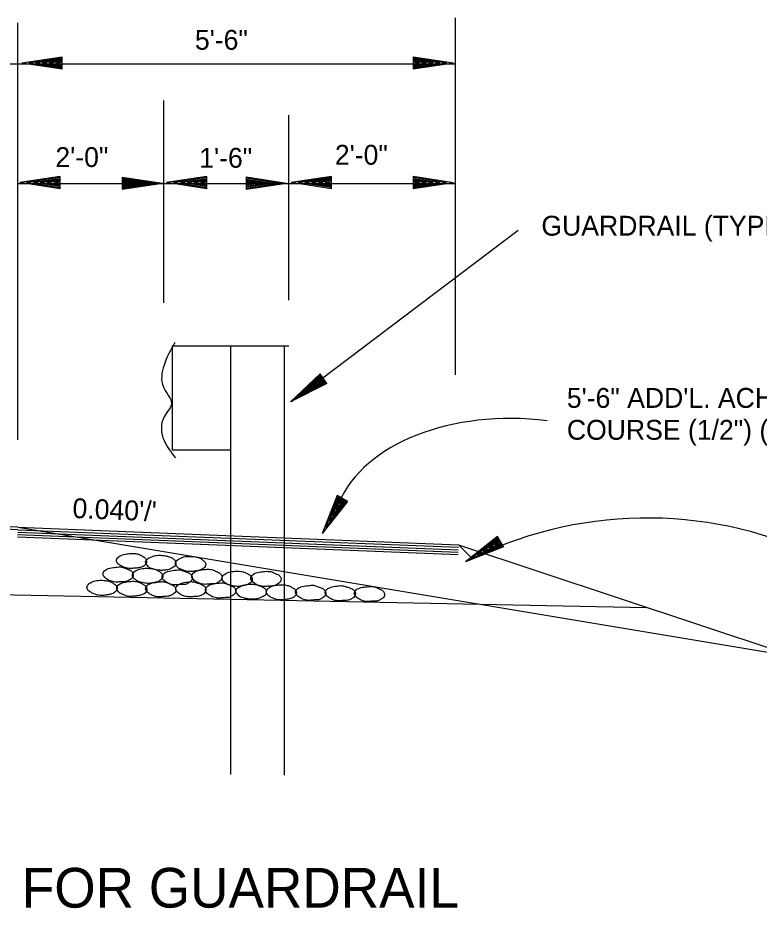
# Model space of a CAD drawing. Extents: x 1373918 to 1374069, y 381000 to 381245.
# Drawn here: x 1373981.14 to 1374003.52, y 381205.43 to 381232.33 of the extents above; entities that cross this region are included whole.
import ezdxf

# ---------------------------------------------------------------- set-up
doc = ezdxf.new("R2010")
doc.units = 0
doc.layers.add('Default', color=7, linetype='Continuous')

msp = doc.modelspace()

# ---------------------------------------------------------------- linework, layer by layer
at = {"layer": 'Default'}
for p, q in [((1373994.349, 381221.542), (1373994.349, 381232.331)), ((1373981.145, 381219.578), (1373981.145, 381232.175)), ((1373961.705, 381230.94), (1373994.349, 381230.94)), ((1373982.481, 381231.144), (1373981.264, 381230.962)), ((1373982.481, 381230.777), (1373981.264, 381230.962)), ((1373982.481, 381231.113), (1373981.468, 381230.962)), ((1373982.481, 381230.809), (1373981.468, 381230.962)), ((1373982.481, 381231.081), (1373981.677, 381230.962)), ((1373982.481, 381230.841), (1373981.677, 381230.962)), ((1373982.481, 381231.052), (1373981.881, 381230.962)), ((1373982.481, 381230.87), (1373981.881, 381230.962)), ((1373982.481, 381231.02), (1373982.085, 381230.962)), ((1373982.481, 381230.901), (1373982.085, 381230.962)), ((1373982.481, 381230.989), (1373982.289, 381230.962)), ((1373982.481, 381230.933), (1373982.289, 381230.962)), ((1373982.481, 381230.777), (1373982.481, 381231.144)), ((1373993.071, 381231.157), (1373994.288, 381230.972)), ((1373993.071, 381231.157), (1373993.071, 381230.79)), ((1373993.071, 381231.125), (1373994.084, 381230.972)), ((1373993.071, 381231.093), (1373993.875, 381230.972)), ((1373993.071, 381231.064), (1373993.671, 381230.972)), ((1373993.071, 381231.033), (1373993.467, 381230.972)), ((1373993.071, 381231.001), (1373993.263, 381230.972)), ((1373993.071, 381230.79), (1373994.288, 381230.972)), ((1373993.071, 381230.914), (1373993.467, 381230.972)), ((1373993.071, 381230.853), (1373993.875, 381230.972)), ((1373993.071, 381230.821), (1373994.084, 381230.972)), ((1373993.071, 381230.882), (1373993.671, 381230.972)), ((1373993.071, 381230.945), (1373993.263, 381230.972)), ((1373985.545, 381223.724), (1373985.545, 381229.835)), ((1373989.319, 381223.803), (1373989.319, 381229.39)), ((1373982.415, 381227.533), (1373981.198, 381227.351)), ((1373982.415, 381227.502), (1373981.402, 381227.351)), ((1373982.415, 381227.47), (1373981.611, 381227.351)), ((1373982.415, 381227.441), (1373981.815, 381227.351)), ((1373982.415, 381227.409), (1373982.019, 381227.351)), ((1373982.415, 381227.166), (1373982.415, 381227.533)), ((1373984.294, 381227.521), (1373985.511, 381227.337)), ((1373984.294, 381227.521), (1373984.294, 381227.154)), ((1373984.294, 381227.49), (1373985.307, 381227.337)), ((1373984.294, 381227.458), (1373985.098, 381227.337)), ((1373984.294, 381227.429), (1373984.894, 381227.337)), ((1373984.294, 381227.397), (1373984.69, 381227.337)), ((1373986.85, 381227.533), (1373985.633, 381227.351)), ((1373986.85, 381227.502), (1373985.837, 381227.351)), ((1373986.85, 381227.47), (1373986.046, 381227.351)), ((1373986.85, 381227.441), (1373986.25, 381227.351)), ((1373986.85, 381227.409), (1373986.454, 381227.351)), ((1373986.85, 381227.166), (1373986.85, 381227.533)), ((1373988.034, 381227.524), (1373989.251, 381227.339)), ((1373988.034, 381227.524), (1373988.034, 381227.157)), ((1373988.034, 381227.492), (1373989.047, 381227.339)), ((1373988.034, 381227.46), (1373988.838, 381227.339)), ((1373988.034, 381227.431), (1373988.634, 381227.339)), ((1373988.034, 381227.4), (1373988.43, 381227.339)), ((1373990.612, 381227.536), (1373989.394, 381227.354)), ((1373990.612, 381227.504), (1373989.599, 381227.354)), ((1373990.612, 381227.473), (1373989.808, 381227.354)), ((1373990.612, 381227.443), (1373990.012, 381227.354)), ((1373990.612, 381227.412), (1373990.216, 381227.354)), ((1373990.612, 381227.169), (1373990.612, 381227.536)), ((1373993.071, 381227.543), (1373994.288, 381227.358)), ((1373993.071, 381227.543), (1373993.071, 381227.176)), ((1373993.071, 381227.512), (1373994.084, 381227.358)), ((1373993.071, 381227.48), (1373993.875, 381227.358)), ((1373993.071, 381227.451), (1373993.671, 381227.358)), ((1373993.071, 381227.419), (1373993.467, 381227.358)), ((1373981.145, 381227.329), (1373994.349, 381227.329)), ((1373982.415, 381227.166), (1373981.198, 381227.351)), ((1373982.415, 381227.198), (1373981.402, 381227.351)), ((1373982.415, 381227.23), (1373981.611, 381227.351)), ((1373982.415, 381227.259), (1373981.815, 381227.351)), ((1373982.415, 381227.29), (1373982.019, 381227.351)), ((1373982.415, 381227.378), (1373982.223, 381227.351)), ((1373982.415, 381227.322), (1373982.223, 381227.351)), ((1373984.294, 381227.366), (1373984.486, 381227.337)), ((1373984.294, 381227.154), (1373985.511, 381227.337)), ((1373984.294, 381227.278), (1373984.69, 381227.337)), ((1373984.294, 381227.217), (1373985.098, 381227.337)), ((1373984.294, 381227.186), (1373985.307, 381227.337)), ((1373984.294, 381227.247), (1373984.894, 381227.337)), ((1373984.294, 381227.31), (1373984.486, 381227.337)), ((1373986.85, 381227.166), (1373985.633, 381227.351)), ((1373986.85, 381227.198), (1373985.837, 381227.351)), ((1373986.85, 381227.23), (1373986.046, 381227.351)), ((1373986.85, 381227.259), (1373986.25, 381227.351)), ((1373986.85, 381227.29), (1373986.454, 381227.351)), ((1373986.85, 381227.378), (1373986.658, 381227.351)), ((1373986.85, 381227.322), (1373986.658, 381227.351)), ((1373988.034, 381227.368), (1373988.226, 381227.339)), ((1373988.034, 381227.157), (1373989.251, 381227.339)), ((1373988.034, 381227.281), (1373988.43, 381227.339)), ((1373988.034, 381227.22), (1373988.838, 381227.339)), ((1373988.034, 381227.188), (1373989.047, 381227.339)), ((1373988.034, 381227.249), (1373988.634, 381227.339)), ((1373988.034, 381227.312), (1373988.226, 381227.339)), ((1373990.612, 381227.169), (1373989.394, 381227.354)), ((1373990.612, 381227.2), (1373989.599, 381227.354)), ((1373990.612, 381227.232), (1373989.808, 381227.354)), ((1373990.612, 381227.261), (1373990.012, 381227.354)), ((1373990.612, 381227.293), (1373990.216, 381227.354)), ((1373990.612, 381227.38), (1373990.42, 381227.354)), ((1373990.612, 381227.324), (1373990.42, 381227.354)), ((1373993.071, 381227.388), (1373993.263, 381227.358)), ((1373993.071, 381227.176), (1373994.288, 381227.358)), ((1373993.071, 381227.3), (1373993.467, 381227.358)), ((1373993.071, 381227.239), (1373993.875, 381227.358)), ((1373993.071, 381227.208), (1373994.084, 381227.358)), ((1373993.071, 381227.269), (1373993.671, 381227.358)), ((1373993.071, 381227.332), (1373993.263, 381227.358)), ((1373989.399, 381220.744), (1373996.245, 381225.917)), ((1373985.798, 381222.423), (1373985.798, 381219.279)), ((1373985.798, 381222.423), (1373989.319, 381222.423)), ((1373987.56, 381222.423), (1373987.56, 381209.466)), ((1373989.178, 381222.409), (1373989.178, 381209.454)), ((1373990.263, 381221.575), (1373989.368, 381220.73)), ((1373990.282, 381221.552), (1373989.534, 381220.844)), ((1373990.302, 381221.522), (1373989.711, 381220.97)), ((1373990.314, 381221.497), (1373989.876, 381221.084)), ((1373990.332, 381221.476), (1373990.041, 381221.201)), ((1373990.469, 381221.279), (1373990.263, 381221.575)), ((1373990.469, 381221.279), (1373989.368, 381220.73)), ((1373990.455, 381221.301), (1373989.534, 381220.844)), ((1373990.433, 381221.328), (1373989.711, 381220.97)), ((1373990.416, 381221.354), (1373989.876, 381221.084)), ((1373990.396, 381221.381), (1373990.041, 381221.201)), ((1373990.349, 381221.449), (1373990.209, 381221.318)), ((1373990.384, 381221.408), (1373990.209, 381221.318)), ((1373985.798, 381219.279), (1373987.56, 381219.279)), ((1373990.78, 381217.903), (1373990.328, 381216.756)), ((1373991.095, 381217.719), (1373990.328, 381216.756)), ((1373990.804, 381217.884), (1373990.43, 381216.934)), ((1373991.071, 381217.736), (1373990.43, 381216.934)), ((1373990.833, 381217.869), (1373990.534, 381217.116)), ((1373991.04, 381217.748), (1373990.534, 381217.116)), ((1373990.857, 381217.855), (1373990.634, 381217.289)), ((1373991.015, 381217.765), (1373990.634, 381217.289)), ((1373990.886, 381217.84), (1373990.738, 381217.468)), ((1373990.989, 381217.779), (1373990.738, 381217.468)), ((1373991.095, 381217.719), (1373990.78, 381217.903)), ((1373990.916, 381217.823), (1373990.843, 381217.643)), ((1373990.962, 381217.796), (1373990.843, 381217.643)), ((1373981.145, 381216.939), (1373966.565, 381217.522)), ((1373981.145, 381216.866), (1373966.565, 381217.449)), ((1373981.145, 381216.939), (1373994.444, 381216.406)), ((1373981.145, 381216.939), (1374004.609, 381213.026)), ((1373981.132, 381216.647), (1373994.432, 381216.115)), ((1373981.135, 381216.72), (1373994.434, 381216.188)), ((1373981.138, 381216.793), (1373994.437, 381216.261)), ((1373981.141, 381216.866), (1373994.44, 381216.334)), ((1373995.615, 381216.666), (1373994.653, 381215.899)), ((1373995.632, 381216.637), (1373994.83, 381215.998)), ((1373995.8, 381216.348), (1373995.615, 381216.666)), ((1373994.444, 381216.406), (1374010.555, 381211.051)), ((1373994.444, 381216.406), (1373994.862, 381215.991)), ((1373995.783, 381216.375), (1373994.83, 381215.998)), ((1373995.647, 381216.611), (1373995.01, 381216.105)), ((1373995.766, 381216.402), (1373995.01, 381216.105)), ((1373995.661, 381216.586), (1373995.185, 381216.207)), ((1373995.751, 381216.426), (1373995.185, 381216.207)), ((1373995.676, 381216.557), (1373995.363, 381216.309)), ((1373995.737, 381216.453), (1373995.363, 381216.309)), ((1373995.693, 381216.53), (1373995.542, 381216.411)), ((1373995.722, 381216.482), (1373995.542, 381216.411)), ((1373995.8, 381216.348), (1373994.653, 381215.899)), ((1373961.266, 381215.293), (1374000.118, 381214.521))]:
    msp.add_line(p, q, dxfattribs=at)
msp.add_arc((1374000.135, 381205.199), 12.021, 64.8876, 117.1378, dxfattribs=at)
msp.add_ellipse((1373996.638, 381216.221), major_axis=(-6.005, 0.733), ratio=0.655798, start_param=4.712389, end_param=6.093533, dxfattribs=at)
for points in [[(1373985.883, 381222.525), (1373985.553, 381221.842), (1373985.536, 381221.177), (1373985.774, 381220.664), (1373985.553, 381220.275), (1373985.553, 381219.558), (1373985.903, 381219.041)], [(1373984.588, 381216.147), (1373984.428, 381216.137), (1373984.233, 381216.079), (1373984.131, 381215.987), (1373984.116, 381215.933), (1373984.165, 381215.836), (1373984.223, 381215.792), (1373984.335, 381215.739), (1373984.491, 381215.695), (1373984.573, 381215.695), (1373984.69, 381215.705), (1373984.821, 381215.72), (1373984.923, 381215.758), (1373985.011, 381215.841), (1373985.025, 381215.904), (1373984.996, 381215.992), (1373984.933, 381216.05), (1373984.865, 381216.089), (1373984.758, 381216.133), (1373984.69, 381216.147), (1373984.588, 381216.147)], [(1373985.459, 381216.095), (1373985.298, 381216.086), (1373985.109, 381216.018), (1373985.012, 381215.94), (1373984.997, 381215.886), (1373985.05, 381215.784), (1373985.094, 381215.731), (1373985.211, 381215.682), (1373985.357, 381215.648), (1373985.439, 381215.639), (1373985.561, 381215.643), (1373985.697, 381215.668), (1373985.794, 381215.711), (1373985.896, 381215.789), (1373985.911, 381215.852), (1373985.881, 381215.94), (1373985.809, 381216.003), (1373985.736, 381216.037), (1373985.629, 381216.071), (1373985.561, 381216.086), (1373985.459, 381216.095)], [(1373986.365, 381216.059), (1373986.205, 381216.054), (1373986.01, 381215.986), (1373985.913, 381215.899), (1373985.898, 381215.84), (1373985.952, 381215.743), (1373986.005, 381215.699), (1373986.112, 381215.651), (1373986.268, 381215.607), (1373986.35, 381215.602), (1373986.467, 381215.612), (1373986.598, 381215.636), (1373986.7, 381215.675), (1373986.798, 381215.753), (1373986.812, 381215.811), (1373986.783, 381215.899), (1373986.71, 381215.957), (1373986.642, 381216.005), (1373986.535, 381216.039), (1373986.467, 381216.054), (1373986.365, 381216.059)], [(1373984.185, 381215.741), (1373984.015, 381215.722), (1373983.826, 381215.673), (1373983.728, 381215.581), (1373983.714, 381215.528), (1373983.762, 381215.426), (1373983.821, 381215.382), (1373983.928, 381215.323), (1373984.083, 381215.285), (1373984.161, 381215.285), (1373984.283, 381215.294), (1373984.419, 381215.304), (1373984.521, 381215.353), (1373984.608, 381215.435), (1373984.623, 381215.498), (1373984.594, 381215.586), (1373984.521, 381215.644), (1373984.453, 381215.673), (1373984.346, 381215.717), (1373984.283, 381215.737), (1373984.185, 381215.741)], [(1373985.067, 381215.7), (1373984.907, 381215.695), (1373984.713, 381215.632), (1373984.615, 381215.54), (1373984.601, 381215.486), (1373984.654, 381215.384), (1373984.708, 381215.34), (1373984.815, 381215.292), (1373984.97, 381215.253), (1373985.053, 381215.243), (1373985.169, 381215.253), (1373985.301, 381215.277), (1373985.403, 381215.316), (1373985.5, 381215.394), (1373985.515, 381215.457), (1373985.485, 381215.545), (1373985.412, 381215.603), (1373985.344, 381215.647), (1373985.238, 381215.681), (1373985.169, 381215.695), (1373985.067, 381215.7)], [(1373985.966, 381215.651), (1373985.805, 381215.636), (1373985.611, 381215.583), (1373985.509, 381215.49), (1373985.494, 381215.437), (1373985.548, 381215.34), (1373985.601, 381215.296), (1373985.713, 381215.233), (1373985.864, 381215.199), (1373985.946, 381215.199), (1373986.063, 381215.208), (1373986.204, 381215.213), (1373986.301, 381215.262), (1373986.393, 381215.345), (1373986.408, 381215.408), (1373986.379, 381215.495), (1373986.311, 381215.553), (1373986.238, 381215.588), (1373986.136, 381215.622), (1373986.068, 381215.651), (1373985.966, 381215.651)], [(1373986.85, 381215.673), (1373986.69, 381215.654), (1373986.5, 381215.605), (1373986.403, 381215.513), (1373986.389, 381215.46), (1373986.442, 381215.357), (1373986.495, 381215.314), (1373986.602, 381215.255), (1373986.758, 381215.217), (1373986.836, 381215.217), (1373986.957, 381215.226), (1373987.088, 381215.236), (1373987.195, 381215.285), (1373987.288, 381215.367), (1373987.302, 381215.43), (1373987.273, 381215.518), (1373987.2, 381215.576), (1373987.127, 381215.605), (1373987.025, 381215.654), (1373986.952, 381215.669), (1373986.85, 381215.673)], [(1373987.769, 381215.61), (1373987.608, 381215.605), (1373987.414, 381215.542), (1373987.317, 381215.45), (1373987.302, 381215.396), (1373987.356, 381215.294), (1373987.409, 381215.251), (1373987.516, 381215.202), (1373987.672, 381215.163), (1373987.754, 381215.153), (1373987.871, 381215.163), (1373988.002, 381215.187), (1373988.104, 381215.226), (1373988.201, 381215.304), (1373988.216, 381215.367), (1373988.187, 381215.455), (1373988.114, 381215.513), (1373988.046, 381215.557), (1373987.939, 381215.591), (1373987.871, 381215.605), (1373987.769, 381215.61)], [(1373988.635, 381215.61), (1373988.474, 381215.591), (1373988.285, 381215.542), (1373988.188, 381215.45), (1373988.173, 381215.396), (1373988.226, 381215.294), (1373988.28, 381215.251), (1373988.387, 381215.192), (1373988.542, 381215.153), (1373988.62, 381215.153), (1373988.742, 381215.163), (1373988.873, 381215.173), (1373988.98, 381215.221), (1373989.072, 381215.304), (1373989.087, 381215.367), (1373989.057, 381215.455), (1373988.985, 381215.513), (1373988.912, 381215.542), (1373988.81, 381215.591), (1373988.737, 381215.605), (1373988.635, 381215.61)], [(1373983.69, 381215.337), (1373983.529, 381215.332), (1373983.335, 381215.264), (1373983.242, 381215.177), (1373983.228, 381215.119), (1373983.276, 381215.021), (1373983.335, 381214.978), (1373983.437, 381214.929), (1373983.597, 381214.885), (1373983.675, 381214.88), (1373983.797, 381214.89), (1373983.928, 381214.914), (1373984.03, 381214.953), (1373984.122, 381215.031), (1373984.137, 381215.089), (1373984.108, 381215.177), (1373984.035, 381215.235), (1373983.967, 381215.284), (1373983.86, 381215.318), (1373983.792, 381215.332), (1373983.69, 381215.337)], [(1373984.589, 381215.309), (1373984.428, 381215.294), (1373984.234, 381215.236), (1373984.142, 381215.148), (1373984.127, 381215.09), (1373984.176, 381214.993), (1373984.224, 381214.949), (1373984.336, 381214.901), (1373984.487, 381214.852), (1373984.569, 381214.852), (1373984.691, 381214.862), (1373984.827, 381214.881), (1373984.924, 381214.915), (1373985.021, 381215.003), (1373985.036, 381215.061), (1373985.007, 381215.148), (1373984.934, 381215.207), (1373984.861, 381215.251), (1373984.759, 381215.289), (1373984.691, 381215.304), (1373984.589, 381215.309)], [(1373985.463, 381215.296), (1373985.302, 381215.276), (1373985.108, 381215.223), (1373985.011, 381215.136), (1373984.996, 381215.077), (1373985.05, 381214.98), (1373985.103, 381214.936), (1373985.21, 381214.878), (1373985.361, 381214.839), (1373985.443, 381214.839), (1373985.565, 381214.849), (1373985.696, 381214.859), (1373985.798, 381214.902), (1373985.895, 381214.99), (1373985.91, 381215.048), (1373985.881, 381215.136), (1373985.808, 381215.194), (1373985.735, 381215.228), (1373985.628, 381215.267), (1373985.565, 381215.291), (1373985.463, 381215.296)], [(1373986.377, 381215.297), (1373986.212, 381215.277), (1373986.018, 381215.224), (1373985.92, 381215.136), (1373985.906, 381215.078), (1373985.959, 381214.981), (1373986.013, 381214.937), (1373986.124, 381214.874), (1373986.275, 381214.84), (1373986.353, 381214.84), (1373986.474, 381214.845), (1373986.61, 381214.859), (1373986.713, 381214.903), (1373986.805, 381214.991), (1373986.819, 381215.049), (1373986.79, 381215.136), (1373986.717, 381215.195), (1373986.644, 381215.229), (1373986.542, 381215.263), (1373986.479, 381215.282), (1373986.377, 381215.297)], [(1373987.273, 381215.26), (1373987.103, 381215.241), (1373986.918, 381215.192), (1373986.816, 381215.1), (1373986.802, 381215.046), (1373986.855, 381214.944), (1373986.909, 381214.901), (1373987.02, 381214.842), (1373987.171, 381214.803), (1373987.249, 381214.803), (1373987.37, 381214.813), (1373987.511, 381214.823), (1373987.608, 381214.871), (1373987.701, 381214.954), (1373987.715, 381215.017), (1373987.686, 381215.105), (1373987.613, 381215.163), (1373987.545, 381215.192), (1373987.438, 381215.231), (1373987.375, 381215.255), (1373987.273, 381215.26)], [(1373988.189, 381215.223), (1373988.029, 381215.213), (1373987.839, 381215.145), (1373987.742, 381215.067), (1373987.727, 381215.014), (1373987.781, 381214.912), (1373987.825, 381214.859), (1373987.941, 381214.81), (1373988.087, 381214.776), (1373988.17, 381214.766), (1373988.291, 381214.771), (1373988.427, 381214.795), (1373988.524, 381214.839), (1373988.627, 381214.917), (1373988.641, 381214.98), (1373988.612, 381215.067), (1373988.539, 381215.131), (1373988.466, 381215.165), (1373988.359, 381215.199), (1373988.291, 381215.213), (1373988.189, 381215.223)], [(1373989.103, 381215.204), (1373988.942, 381215.19), (1373988.748, 381215.131), (1373988.656, 381215.044), (1373988.641, 381214.986), (1373988.69, 381214.888), (1373988.738, 381214.845), (1373988.85, 381214.796), (1373989.001, 381214.748), (1373989.083, 381214.748), (1373989.205, 381214.757), (1373989.341, 381214.777), (1373989.438, 381214.811), (1373989.535, 381214.898), (1373989.55, 381214.957), (1373989.521, 381215.044), (1373989.448, 381215.102), (1373989.375, 381215.146), (1373989.273, 381215.185), (1373989.205, 381215.2), (1373989.103, 381215.204)], [(1373989.99, 381215.19), (1373989.829, 381215.17), (1373989.635, 381215.117), (1373989.538, 381215.029), (1373989.523, 381214.971), (1373989.577, 381214.874), (1373989.63, 381214.83), (1373989.737, 381214.772), (1373989.888, 381214.733), (1373989.97, 381214.733), (1373990.092, 381214.743), (1373990.223, 381214.752), (1373990.325, 381214.796), (1373990.422, 381214.884), (1373990.437, 381214.942), (1373990.408, 381215.029), (1373990.335, 381215.088), (1373990.262, 381215.122), (1373990.155, 381215.161), (1373990.092, 381215.185), (1373989.99, 381215.19)], [(1373990.89, 381215.178), (1373990.724, 381215.158), (1373990.53, 381215.105), (1373990.433, 381215.017), (1373990.418, 381214.959), (1373990.472, 381214.862), (1373990.525, 381214.818), (1373990.637, 381214.755), (1373990.788, 381214.721), (1373990.865, 381214.721), (1373990.987, 381214.726), (1373991.123, 381214.74), (1373991.225, 381214.784), (1373991.317, 381214.871), (1373991.332, 381214.93), (1373991.303, 381215.017), (1373991.23, 381215.076), (1373991.157, 381215.11), (1373991.055, 381215.144), (1373990.992, 381215.163), (1373990.89, 381215.178)], [(1373991.767, 381215.153), (1373991.597, 381215.133), (1373991.407, 381215.084), (1373991.31, 381214.992), (1373991.295, 381214.939), (1373991.349, 381214.841), (1373991.402, 381214.798), (1373991.509, 381214.739), (1373991.665, 381214.696), (1373991.743, 381214.696), (1373991.864, 381214.71), (1373992, 381214.715), (1373992.102, 381214.764), (1373992.195, 381214.846), (1373992.209, 381214.91), (1373992.18, 381214.997), (1373992.107, 381215.055), (1373992.034, 381215.089), (1373991.932, 381215.128), (1373991.864, 381215.148), (1373991.767, 381215.153)]]:
    msp.add_spline(points, degree=3, dxfattribs=at)

# ---------------------------------------------------------------- texts
for s, height, p in [('5\'-6"', 0.6, (1373986.486, 381231.366)), ('2\'-0"', 0.6, (1373990.711, 381227.893)), ('2\'-0"', 0.6, (1373982.275, 381227.823)), ('1\'-6"', 0.6, (1373986.617, 381227.801)), ('GUARDRAIL (TYPE A)', 0.6, (1373996.944, 381225.75)), ('5\'-6" ADD\'L. ACHM SURFACE ', 0.6, (1373997.713, 381220.548)), ('COURSE (1/2") (220 LBS. PER SQ. YD.)', 0.6, (1373997.713, 381219.584)), ('WIDENING FOR GUARDRAIL', 1.2, (1373972.613, 381205.449))]:
    msp.add_text(s, height=height, dxfattribs=at).set_placement(p)
msp.add_text("0.040'/'", height=0.6, rotation=357.7094, dxfattribs=at).set_placement((1373982.782, 381217.221))

doc.saveas('drawing.dxf')
